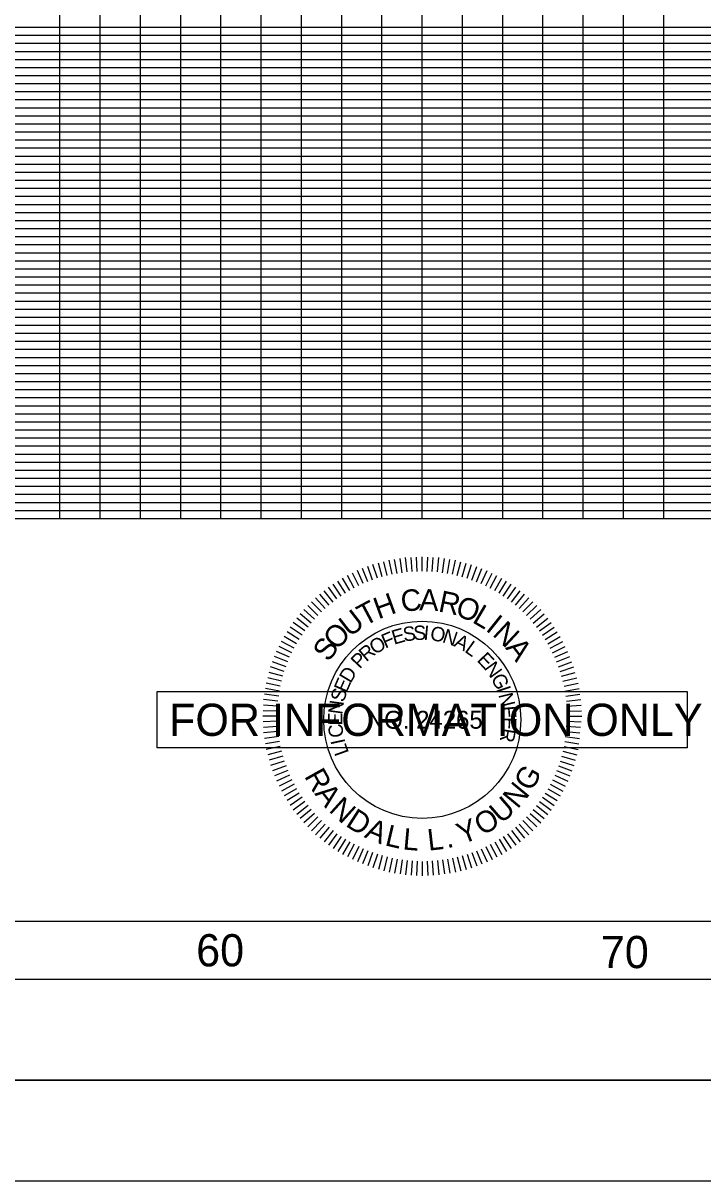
# Model space of a CAD drawing. Extents: x -15 to 165, y -6 to 109.
# Drawn here: x 135.09 to 151.97, y -6.45 to 22.3 of the extents above; entities that cross this region are included whole.
import ezdxf

# ---------------------------------------------------------------- set-up
doc = ezdxf.new("R2010")
doc.units = 0
for name, color, linetype in [('RD_SHT_Bndy', 7, 'Continuous'), ('RD_SHT_IplotShp', 7, 'Continuous'), ('RD_SHT_MjGrid', 7, 'Continuous'), ('RD_SHT_MnGrid', 7, 'Continuous'), ('RD_SHT_SubGrid', 7, 'Continuous'), ('RD_SHT_TX', 7, 'Continuous'), ('RD_TX_PEShield', 7, 'Continuous'), ('RD_XS_TX_Notes', 7, 'Continuous')]:
    doc.layers.add(name, color=color, linetype=linetype)

msp = doc.modelspace()

# ---------------------------------------------------------------- linework, layer by layer
at = {"layer": 'RD_SHT_Bndy'}
for p, q in [((-12.73, -3.949), (163.27, -3.949)), ((-12.73, -6.449), (163.27, -6.449))]:
    msp.add_line(p, q, dxfattribs=at)
msp.add_lwpolyline([(-4.99, 103.551), (162.51, 103.551), (162.51, -1.449), (-4.99, -1.449)], close=True, dxfattribs=at)
at = {"layer": 'RD_SHT_IplotShp'}
msp.add_lwpolyline([(-14.589, 106.051), (165.01, 106.051), (165.01, -3.949), (-14.589, -3.949)], close=True, dxfattribs=at)
at = {"layer": 'RD_SHT_MjGrid'}
for p, q in [((140, 10), (140, 100)), ((145, 10), (145, 100)), ((150, 10), (150, 100)), ((0, 20), (160, 20)), ((0, 15), (160, 15)), ((0, 10), (160, 10)), ((0, 0), (160, 0))]:
    msp.add_line(p, q, dxfattribs=at)
at = {"layer": 'RD_SHT_MnGrid'}
for p, q in [((136, 10), (136, 100)), ((137, 10), (137, 100)), ((138, 10), (138, 100)), ((139, 10), (139, 100)), ((141, 10), (141, 100)), ((142, 10), (142, 100)), ((143, 10), (143, 100)), ((144, 10), (144, 100)), ((146, 10), (146, 100)), ((147, 10), (147, 100)), ((148, 10), (148, 100)), ((149, 10), (149, 100)), ((151, 10), (151, 100)), ((0, 22), (160, 22)), ((0, 21), (160, 21)), ((0, 19), (160, 19)), ((0, 18), (160, 18)), ((0, 17), (160, 17)), ((0, 16), (160, 16)), ((0, 14), (160, 14)), ((0, 13), (160, 13)), ((0, 12), (160, 12)), ((0, 11), (160, 11))]:
    msp.add_line(p, q, dxfattribs=at)
at = {"layer": 'RD_SHT_SubGrid'}
for p, q in [((0, 22.2), (160, 22.2)), ((0, 21.8), (160, 21.8)), ((0, 21.6), (160, 21.6)), ((0, 21.4), (160, 21.4)), ((0, 21.2), (160, 21.2)), ((0, 20.8), (160, 20.8)), ((0, 20.6), (160, 20.6)), ((0, 20.4), (160, 20.4)), ((0, 20.2), (160, 20.2)), ((0, 19.8), (160, 19.8)), ((0, 19.6), (160, 19.6)), ((0, 19.4), (160, 19.4)), ((0, 19.2), (160, 19.2)), ((0, 18.8), (160, 18.8)), ((0, 18.6), (160, 18.6)), ((0, 18.4), (160, 18.4)), ((0, 18.2), (160, 18.2)), ((0, 17.8), (160, 17.8)), ((0, 17.6), (160, 17.6)), ((0, 17.4), (160, 17.4)), ((0, 17.2), (160, 17.2)), ((0, 16.8), (160, 16.8)), ((0, 16.6), (160, 16.6)), ((0, 16.4), (160, 16.4)), ((0, 16.2), (160, 16.2)), ((0, 15.8), (160, 15.8)), ((0, 15.6), (160, 15.6)), ((0, 15.4), (160, 15.4)), ((0, 15.2), (160, 15.2)), ((0, 14.8), (160, 14.8)), ((0, 14.6), (160, 14.6)), ((0, 14.4), (160, 14.4)), ((0, 14.2), (160, 14.2)), ((0, 13.8), (160, 13.8)), ((0, 13.6), (160, 13.6)), ((0, 13.4), (160, 13.4)), ((0, 13.2), (160, 13.2)), ((0, 12.8), (160, 12.8)), ((0, 12.6), (160, 12.6)), ((0, 12.4), (160, 12.4)), ((0, 12.2), (160, 12.2)), ((0, 11.8), (160, 11.8)), ((0, 11.6), (160, 11.6)), ((0, 11.4), (160, 11.4)), ((0, 11.2), (160, 11.2)), ((0, 10.8), (160, 10.8)), ((0, 10.6), (160, 10.6)), ((0, 10.4), (160, 10.4)), ((0, 10.2), (160, 10.2))]:
    msp.add_line(p, q, dxfattribs=at)
at = {"layer": 'RD_TX_PEShield'}
for p, q in [((144.129, 8.581), (144.043, 8.926)), ((144.129, 8.581), (144.043, 8.926)), ((144.251, 8.614), (144.177, 8.962)), ((144.251, 8.614), (144.177, 8.962)), ((144.375, 8.633), (144.313, 8.983)), ((144.375, 8.633), (144.313, 8.983)), ((144.499, 8.653), (144.449, 9.005)), ((144.499, 8.653), (144.449, 9.005)), ((144.623, 8.673), (144.586, 9.027)), ((144.623, 8.673), (144.586, 9.027)), ((144.749, 8.679), (144.724, 9.034)), ((144.749, 8.679), (144.724, 9.034)), ((144.874, 8.686), (144.862, 9.041)), ((144.874, 8.686), (144.862, 9.041)), ((145, 8.692), (145, 9.048)), ((145, 8.692), (145, 9.048)), ((145.126, 8.686), (145.138, 9.041)), ((145.126, 8.686), (145.138, 9.041)), ((145.251, 8.679), (145.276, 9.034)), ((145.251, 8.679), (145.276, 9.034)), ((145.377, 8.673), (145.414, 9.027)), ((145.377, 8.673), (145.414, 9.027)), ((145.501, 8.653), (145.551, 9.005)), ((145.501, 8.653), (145.551, 9.005)), ((145.625, 8.633), (145.687, 8.983)), ((145.625, 8.633), (145.687, 8.983)), ((145.749, 8.614), (145.823, 8.962)), ((145.749, 8.614), (145.823, 8.962)), ((145.749, 8.614), (145.823, 8.962)), ((145.871, 8.581), (145.957, 8.926)), ((145.871, 8.581), (145.957, 8.926)), ((145.871, 8.581), (145.957, 8.926)), ((143.422, 8.324), (143.266, 8.643)), ((143.422, 8.324), (143.266, 8.643)), ((143.534, 8.381), (143.389, 8.706)), ((143.534, 8.381), (143.389, 8.706)), ((143.651, 8.426), (143.518, 8.755)), ((143.651, 8.426), (143.518, 8.755)), ((143.769, 8.471), (143.647, 8.805)), ((143.769, 8.471), (143.647, 8.805)), ((143.886, 8.516), (143.776, 8.854)), ((143.886, 8.516), (143.776, 8.854)), ((144.008, 8.548), (143.91, 8.89)), ((144.008, 8.548), (143.91, 8.89)), ((145.992, 8.548), (146.09, 8.89)), ((145.992, 8.548), (146.09, 8.89)), ((145.992, 8.548), (146.09, 8.89)), ((146.114, 8.516), (146.224, 8.854)), ((146.114, 8.516), (146.224, 8.854)), ((146.114, 8.516), (146.224, 8.854)), ((146.231, 8.471), (146.353, 8.805)), ((146.231, 8.471), (146.353, 8.805)), ((146.231, 8.471), (146.353, 8.805)), ((146.349, 8.426), (146.482, 8.755)), ((146.349, 8.426), (146.482, 8.755)), ((146.349, 8.426), (146.482, 8.755)), ((146.466, 8.381), (146.611, 8.706)), ((146.466, 8.381), (146.611, 8.706)), ((146.466, 8.381), (146.611, 8.706)), ((146.578, 8.324), (146.734, 8.643)), ((146.578, 8.324), (146.734, 8.643)), ((146.578, 8.324), (146.734, 8.643)), ((142.987, 8.072), (142.788, 8.367)), ((142.987, 8.072), (142.788, 8.367)), ((143.092, 8.141), (142.904, 8.442)), ((143.092, 8.141), (142.904, 8.442)), ((143.198, 8.209), (143.02, 8.518)), ((143.198, 8.209), (143.02, 8.518)), ((143.31, 8.267), (143.143, 8.58)), ((143.31, 8.267), (143.143, 8.58)), ((146.69, 8.267), (146.857, 8.58)), ((146.69, 8.267), (146.857, 8.58)), ((146.69, 8.267), (146.857, 8.58)), ((146.802, 8.209), (146.98, 8.518)), ((146.802, 8.209), (146.98, 8.518)), ((146.802, 8.209), (146.98, 8.518)), ((146.908, 8.141), (147.096, 8.442)), ((146.908, 8.141), (147.096, 8.442)), ((146.908, 8.141), (147.096, 8.442)), ((147.013, 8.072), (147.212, 8.367)), ((147.013, 8.072), (147.212, 8.367)), ((147.013, 8.072), (147.212, 8.367)), ((142.686, 7.846), (142.457, 8.118)), ((142.686, 7.846), (142.457, 8.118)), ((142.784, 7.925), (142.565, 8.205)), ((142.784, 7.925), (142.565, 8.205)), ((142.881, 8.004), (142.672, 8.292)), ((142.881, 8.004), (142.672, 8.292)), ((147.119, 8.004), (147.328, 8.292)), ((147.119, 8.004), (147.328, 8.292)), ((147.119, 8.004), (147.328, 8.292)), ((147.216, 7.925), (147.435, 8.205)), ((147.216, 7.925), (147.435, 8.205)), ((147.216, 7.925), (147.435, 8.205)), ((147.314, 7.846), (147.543, 8.118)), ((147.314, 7.846), (147.543, 8.118)), ((147.314, 7.846), (147.543, 8.118)), ((142.41, 7.589), (142.155, 7.836)), ((142.41, 7.589), (142.155, 7.836)), ((142.499, 7.678), (142.252, 7.933)), ((142.499, 7.678), (142.252, 7.933)), ((142.588, 7.766), (142.35, 8.031)), ((142.588, 7.766), (142.35, 8.031)), ((147.412, 7.766), (147.65, 8.031)), ((147.412, 7.766), (147.65, 8.031)), ((147.412, 7.766), (147.65, 8.031)), ((147.501, 7.678), (147.748, 7.933)), ((147.501, 7.678), (147.748, 7.933)), ((147.501, 7.678), (147.748, 7.933)), ((147.59, 7.589), (147.845, 7.836)), ((147.59, 7.589), (147.845, 7.836)), ((147.59, 7.589), (147.845, 7.836)), ((142.163, 7.304), (141.883, 7.523)), ((142.163, 7.304), (141.883, 7.523)), ((142.242, 7.402), (141.97, 7.63)), ((142.242, 7.402), (141.97, 7.63)), ((142.321, 7.5), (142.057, 7.738)), ((142.321, 7.5), (142.057, 7.738)), ((147.679, 7.5), (147.943, 7.738)), ((147.679, 7.5), (147.943, 7.738)), ((147.679, 7.5), (147.943, 7.738)), ((147.758, 7.402), (148.03, 7.63)), ((147.758, 7.402), (148.03, 7.63)), ((147.758, 7.402), (148.03, 7.63)), ((147.837, 7.304), (148.117, 7.523)), ((147.837, 7.304), (148.117, 7.523)), ((147.837, 7.304), (148.117, 7.523)), ((142.015, 7.101), (141.721, 7.3)), ((142.015, 7.101), (141.721, 7.3)), ((142.084, 7.206), (141.796, 7.416)), ((142.084, 7.206), (141.796, 7.416)), ((147.916, 7.206), (148.204, 7.416)), ((147.916, 7.206), (148.204, 7.416)), ((147.916, 7.206), (148.204, 7.416)), ((147.985, 7.101), (148.279, 7.3)), ((147.985, 7.101), (148.279, 7.3)), ((147.985, 7.101), (148.279, 7.3)), ((141.821, 6.778), (141.507, 6.945)), ((141.821, 6.778), (141.507, 6.945)), ((141.878, 6.89), (141.57, 7.068)), ((141.878, 6.89), (141.57, 7.068)), ((141.947, 6.996), (141.645, 7.184)), ((141.947, 6.996), (141.645, 7.184)), ((148.053, 6.996), (148.355, 7.184)), ((148.053, 6.996), (148.355, 7.184)), ((148.053, 6.996), (148.355, 7.184)), ((148.122, 6.89), (148.43, 7.068)), ((148.122, 6.89), (148.43, 7.068)), ((148.122, 6.89), (148.43, 7.068)), ((148.179, 6.778), (148.493, 6.945)), ((148.179, 6.778), (148.493, 6.945)), ((148.179, 6.778), (148.493, 6.945)), ((141.707, 6.554), (141.382, 6.699)), ((141.707, 6.554), (141.382, 6.699)), ((141.764, 6.666), (141.445, 6.822)), ((141.764, 6.666), (141.445, 6.822)), ((148.236, 6.666), (148.555, 6.822)), ((148.236, 6.666), (148.555, 6.822)), ((148.236, 6.666), (148.555, 6.822)), ((148.293, 6.554), (148.618, 6.699)), ((148.293, 6.554), (148.618, 6.699)), ((148.293, 6.554), (148.618, 6.699)), ((141.617, 6.319), (141.283, 6.441)), ((141.617, 6.319), (141.283, 6.441)), ((141.662, 6.436), (141.332, 6.57)), ((141.662, 6.436), (141.332, 6.57)), ((148.338, 6.436), (148.668, 6.57)), ((148.338, 6.436), (148.668, 6.57)), ((148.338, 6.436), (148.668, 6.57)), ((148.383, 6.319), (148.717, 6.441)), ((148.383, 6.319), (148.717, 6.441)), ((148.383, 6.319), (148.717, 6.441)), ((141.507, 5.959), (141.162, 6.045)), ((141.507, 5.959), (141.162, 6.045)), ((141.539, 6.08), (141.198, 6.178)), ((141.539, 6.08), (141.198, 6.178)), ((141.572, 6.202), (141.233, 6.312)), ((141.572, 6.202), (141.233, 6.312)), ((148.428, 6.202), (148.767, 6.312)), ((148.428, 6.202), (148.767, 6.312)), ((148.428, 6.202), (148.767, 6.312)), ((148.461, 6.08), (148.802, 6.178)), ((148.461, 6.08), (148.802, 6.178)), ((148.461, 6.08), (148.802, 6.178)), ((148.493, 5.959), (148.838, 6.045)), ((148.493, 5.959), (148.838, 6.045)), ((148.493, 5.959), (148.838, 6.045)), ((141.455, 5.713), (141.104, 5.775)), ((141.455, 5.713), (141.104, 5.775)), ((141.474, 5.837), (141.126, 5.911)), ((141.474, 5.837), (141.126, 5.911)), ((148.526, 5.837), (148.874, 5.911)), ((148.526, 5.837), (148.874, 5.911)), ((148.526, 5.837), (148.874, 5.911)), ((148.545, 5.713), (148.896, 5.775)), ((148.545, 5.713), (148.896, 5.775)), ((148.545, 5.713), (148.896, 5.775)), ((141.415, 5.465), (141.061, 5.502)), ((141.415, 5.465), (141.061, 5.502)), ((141.435, 5.589), (141.083, 5.638)), ((141.435, 5.589), (141.083, 5.638)), ((148.565, 5.589), (148.917, 5.638)), ((148.565, 5.589), (148.917, 5.638)), ((148.565, 5.589), (148.917, 5.638)), ((148.585, 5.465), (148.939, 5.502)), ((148.585, 5.465), (148.939, 5.502)), ((148.585, 5.465), (148.939, 5.502)), ((141.402, 5.213), (141.047, 5.226)), ((141.402, 5.213), (141.047, 5.226)), ((141.409, 5.339), (141.054, 5.364)), ((141.409, 5.339), (141.054, 5.364)), ((148.591, 5.339), (148.946, 5.364)), ((148.591, 5.339), (148.946, 5.364)), ((148.591, 5.339), (148.946, 5.364)), ((148.598, 5.213), (148.953, 5.226)), ((148.598, 5.213), (148.953, 5.226)), ((148.598, 5.213), (148.953, 5.226)), ((141.396, 5.088), (141.04, 5.088)), ((141.396, 5.088), (141.04, 5.088)), ((141.402, 4.962), (141.047, 4.95)), ((141.402, 4.962), (141.047, 4.95)), ((148.591, 4.962), (148.946, 4.95)), ((148.591, 4.962), (148.946, 4.95)), ((148.605, 5.088), (148.961, 5.088)), ((148.605, 5.088), (148.961, 5.088)), ((148.605, 5.088), (148.961, 5.088)), ((141.409, 4.837), (141.054, 4.812)), ((141.409, 4.837), (141.054, 4.812)), ((141.415, 4.711), (141.061, 4.674)), ((141.415, 4.711), (141.061, 4.674)), ((148.565, 4.713), (148.917, 4.676)), ((148.565, 4.713), (148.917, 4.676)), ((148.578, 4.838), (148.932, 4.813)), ((148.578, 4.838), (148.932, 4.813)), ((141.435, 4.587), (141.083, 4.537)), ((141.435, 4.587), (141.083, 4.537)), ((141.455, 4.463), (141.104, 4.401)), ((141.455, 4.463), (141.104, 4.401)), ((141.474, 4.338), (141.126, 4.264)), ((141.474, 4.338), (141.126, 4.264)), ((148.526, 4.338), (148.874, 4.264)), ((148.526, 4.338), (148.874, 4.264)), ((148.539, 4.464), (148.888, 4.402)), ((148.539, 4.464), (148.888, 4.402)), ((148.552, 4.589), (148.903, 4.539)), ((148.552, 4.589), (148.903, 4.539)), ((141.507, 4.217), (141.162, 4.131)), ((141.507, 4.217), (141.162, 4.131)), ((141.539, 4.095), (141.198, 3.997)), ((141.539, 4.095), (141.198, 3.997)), ((148.461, 4.095), (148.802, 3.997)), ((148.461, 4.095), (148.802, 3.997)), ((148.493, 4.217), (148.838, 4.131)), ((148.493, 4.217), (148.838, 4.131)), ((141.572, 3.974), (141.233, 3.864)), ((141.617, 3.856), (141.283, 3.735)), ((141.617, 3.856), (141.283, 3.735)), ((141.662, 3.739), (141.332, 3.606)), ((141.662, 3.739), (141.332, 3.606)), ((148.338, 3.739), (148.668, 3.606)), ((148.338, 3.739), (148.668, 3.606)), ((148.383, 3.856), (148.717, 3.735)), ((148.383, 3.856), (148.717, 3.735)), ((148.428, 3.974), (148.767, 3.864)), ((148.428, 3.974), (148.767, 3.864)), ((141.707, 3.622), (141.382, 3.477)), ((141.707, 3.622), (141.382, 3.477)), ((141.764, 3.51), (141.445, 3.354)), ((141.764, 3.51), (141.445, 3.354)), ((148.236, 3.51), (148.555, 3.354)), ((148.236, 3.51), (148.555, 3.354)), ((148.293, 3.622), (148.618, 3.477)), ((148.293, 3.622), (148.618, 3.477)), ((141.821, 3.398), (141.507, 3.231)), ((141.821, 3.398), (141.507, 3.231)), ((141.878, 3.286), (141.57, 3.108)), ((141.878, 3.286), (141.57, 3.108)), ((141.947, 3.18), (141.645, 2.992)), ((141.947, 3.18), (141.645, 2.992)), ((148.053, 3.18), (148.355, 2.992)), ((148.053, 3.18), (148.355, 2.992)), ((148.122, 3.286), (148.43, 3.108)), ((148.122, 3.286), (148.43, 3.108)), ((148.179, 3.398), (148.493, 3.231)), ((148.179, 3.398), (148.493, 3.231)), ((142.015, 3.075), (141.721, 2.876)), ((142.015, 3.075), (141.721, 2.876)), ((142.084, 2.969), (141.796, 2.76)), ((142.084, 2.969), (141.796, 2.76)), ((147.916, 2.969), (148.204, 2.76)), ((147.916, 2.969), (148.204, 2.76)), ((147.985, 3.075), (148.279, 2.876)), ((147.985, 3.075), (148.279, 2.876)), ((142.163, 2.871), (141.883, 2.652)), ((142.163, 2.871), (141.883, 2.652)), ((142.242, 2.774), (141.97, 2.545)), ((142.242, 2.774), (141.97, 2.545)), ((142.321, 2.676), (142.057, 2.438)), ((142.321, 2.676), (142.057, 2.438)), ((147.679, 2.676), (147.943, 2.438)), ((147.679, 2.676), (147.943, 2.438)), ((147.758, 2.774), (148.03, 2.545)), ((147.758, 2.774), (148.03, 2.545)), ((147.837, 2.871), (148.117, 2.652)), ((147.837, 2.871), (148.117, 2.652)), ((142.41, 2.587), (142.155, 2.34)), ((142.41, 2.587), (142.155, 2.34)), ((142.499, 2.498), (142.252, 2.242)), ((142.499, 2.498), (142.252, 2.242)), ((142.588, 2.409), (142.35, 2.145)), ((142.588, 2.409), (142.35, 2.145)), ((142.686, 2.33), (142.457, 2.058)), ((142.686, 2.33), (142.457, 2.058)), ((147.314, 2.33), (147.543, 2.058)), ((147.314, 2.33), (147.543, 2.058)), ((147.412, 2.409), (147.65, 2.145)), ((147.501, 2.498), (147.748, 2.242)), ((147.501, 2.498), (147.748, 2.242)), ((147.59, 2.587), (147.845, 2.34)), ((147.59, 2.587), (147.845, 2.34)), ((142.784, 2.251), (142.565, 1.971)), ((142.784, 2.251), (142.565, 1.971)), ((142.881, 2.172), (142.672, 1.884)), ((142.881, 2.172), (142.672, 1.884)), ((142.987, 2.103), (142.788, 1.808)), ((142.987, 2.103), (142.788, 1.808)), ((143.092, 2.035), (142.904, 1.733)), ((143.092, 2.035), (142.904, 1.733)), ((146.908, 2.035), (147.096, 1.733)), ((146.908, 2.035), (147.096, 1.733)), ((147.013, 2.103), (147.212, 1.808)), ((147.013, 2.103), (147.212, 1.808)), ((147.119, 2.172), (147.328, 1.884)), ((147.119, 2.172), (147.328, 1.884)), ((147.216, 2.251), (147.435, 1.971)), ((147.216, 2.251), (147.435, 1.971)), ((143.198, 1.966), (143.02, 1.658)), ((143.198, 1.966), (143.02, 1.658)), ((143.31, 1.909), (143.143, 1.595)), ((143.31, 1.909), (143.143, 1.595)), ((143.422, 1.852), (143.266, 1.532)), ((143.422, 1.852), (143.266, 1.532)), ((143.534, 1.795), (143.389, 1.47)), ((143.534, 1.795), (143.389, 1.47)), ((143.651, 1.75), (143.518, 1.42)), ((143.651, 1.75), (143.518, 1.42)), ((146.349, 1.75), (146.482, 1.42)), ((146.349, 1.75), (146.482, 1.42)), ((146.466, 1.795), (146.611, 1.47)), ((146.466, 1.795), (146.611, 1.47)), ((146.578, 1.852), (146.734, 1.532)), ((146.578, 1.852), (146.734, 1.532)), ((146.69, 1.909), (146.857, 1.595)), ((146.69, 1.909), (146.857, 1.595)), ((146.802, 1.966), (146.98, 1.658)), ((146.802, 1.966), (146.98, 1.658)), ((143.769, 1.705), (143.647, 1.371)), ((143.769, 1.705), (143.647, 1.371)), ((143.886, 1.66), (143.776, 1.321)), ((143.886, 1.66), (143.776, 1.321)), ((144.008, 1.627), (143.91, 1.285)), ((144.008, 1.627), (143.91, 1.285)), ((144.129, 1.595), (144.043, 1.25)), ((144.129, 1.595), (144.043, 1.25)), ((144.251, 1.562), (144.177, 1.214)), ((144.251, 1.562), (144.177, 1.214)), ((144.375, 1.542), (144.313, 1.192)), ((144.375, 1.542), (144.313, 1.192)), ((144.499, 1.523), (144.449, 1.171)), ((144.499, 1.523), (144.449, 1.171)), ((144.623, 1.503), (144.586, 1.149)), ((144.623, 1.503), (144.586, 1.149)), ((144.749, 1.496), (144.724, 1.142)), ((144.749, 1.496), (144.724, 1.142)), ((144.874, 1.49), (144.862, 1.135)), ((144.874, 1.49), (144.862, 1.135)), ((145, 1.483), (145, 1.127)), ((145, 1.483), (145, 1.127)), ((145.126, 1.49), (145.138, 1.135)), ((145.126, 1.49), (145.138, 1.135)), ((145.251, 1.496), (145.276, 1.142)), ((145.251, 1.496), (145.276, 1.142)), ((145.377, 1.503), (145.414, 1.149)), ((145.377, 1.503), (145.414, 1.149)), ((145.501, 1.523), (145.551, 1.171)), ((145.501, 1.523), (145.551, 1.171)), ((145.625, 1.542), (145.687, 1.192)), ((145.625, 1.542), (145.687, 1.192)), ((145.749, 1.562), (145.823, 1.214)), ((145.749, 1.562), (145.823, 1.214)), ((145.871, 1.595), (145.957, 1.25)), ((145.871, 1.595), (145.957, 1.25)), ((145.992, 1.627), (146.09, 1.285)), ((145.992, 1.627), (146.09, 1.285)), ((146.114, 1.66), (146.224, 1.321)), ((146.114, 1.66), (146.224, 1.321)), ((146.231, 1.705), (146.353, 1.371)), ((146.231, 1.705), (146.353, 1.371))]:
    msp.add_line(p, q, dxfattribs=at)
msp.add_circle((145, 5), 2.448, dxfattribs=at)
at = {"layer": 'RD_XS_TX_Notes'}
msp.add_lwpolyline([(138.418, 5.7), (151.582, 5.7), (151.582, 4.3), (138.418, 4.3)], close=True, dxfattribs=at)

# ---------------------------------------------------------------- texts
at = {"layer": 'RD_SHT_TX'}
for s, p in [('60', (139.385, -1.123)), ('70', (149.438, -1.167))]:
    msp.add_text(s, height=0.8, dxfattribs=at).set_placement(p)
at = {"layer": 'RD_TX_PEShield'}
for s, height, rotation, p in [('H', 0.534, 19.9102, (143.91, 7.492)), ('C', 0.534, 6.8832, (144.499, 7.674)), ('A', 0.534, 357.9448, (144.921, 7.719)), ('R', 0.534, 348.267, (145.379, 7.694)), ('O', 0.534, 339.3286, (145.793, 7.602)), ('T', 0.534, 28.0947, (143.566, 7.312)), ('L', 0.534, 329.6507, (146.219, 7.432)), ('U', 0.534, 37.7726, (143.198, 7.038)), ('I', 0.534, 321.4663, (146.553, 7.233)), ('O', 0.534, 47.4504, (142.881, 6.706)), ('F', 0.356, 23.0853, (144.081, 6.766)), ('E', 0.356, 16.1843, (144.3, 6.863)), ('S', 0.356, 8.6909, (144.549, 6.939)), ('S', 0.356, 1.79, (144.785, 6.979)), ('I', 0.356, 354.889, (145.024, 6.99)), ('O', 0.356, 350.4045, (145.18, 6.982)), ('N', 0.356, 341.7029, (145.478, 6.932)), ('N', 0.534, 317.0007, (146.722, 7.106)), ('S', 0.534, 54.9027, (142.678, 6.416)), ('O', 0.356, 31.7869, (143.824, 6.606)), ('A', 0.356, 333.0013, (145.765, 6.838)), ('L', 0.356, 324.2997, (146.034, 6.701)), ('A', 0.534, 307.3229, (147.052, 6.786)), ('P', 0.356, 46.7912, (143.449, 6.247)), ('R', 0.356, 39.8902, (143.61, 6.425)), ('E', 0.356, 313.2251, (146.341, 6.471)), ('N', 0.356, 305.7317, (146.522, 6.283)), ('E', 0.356, 66.5674, (143.118, 5.649)), ('D', 0.356, 59.074, (143.219, 5.889)), ('G', 0.356, 297.0301, (146.698, 6.038)), ('S', 0.356, 73.4683, (143.054, 5.418)), ('I', 0.356, 288.3285, (146.836, 5.769)), ('N', 0.356, 82.17, (143.013, 5.119)), ('N', 0.356, 283.8441, (146.89, 5.624)), ('E', 0.356, 275.1424, (146.963, 5.33)), ('E', 0.356, 89.6633, (143.014, 4.859)), ('C', 0.356, 97.7667, (143.054, 4.58)), ('E', 0.356, 267.6491, (146.989, 5.072)), ('R', 0.356, 260.1557, (146.982, 4.811)), ('I', 0.356, 102.2511, (143.093, 4.429)), ('L', 0.356, 109.7445, (143.184, 4.185)), ('R', 0.534, 299.1493, (142.06, 3.603)), ('G', 0.534, 60.1113, (147.711, 3.198)), ('N', 0.534, 50.4335, (147.369, 2.768)), ('A', 0.534, 308.0877, (142.313, 3.163)), ('N', 0.534, 317.7655, (142.66, 2.737)), ('U', 0.534, 40.7556, (146.96, 2.401)), ('D', 0.534, 327.4433, (143.073, 2.376)), ('O', 0.534, 31.0778, (146.496, 2.108)), ('A', 0.534, 337.1212, (143.542, 2.089)), ('L', 0.534, 346.799, (144.052, 1.886)), ('L', 0.534, 354.9835, (144.505, 1.782)), ('Y', 0.534, 21.4, (145.988, 1.898)), ('L', 0.534, 6.5171, (145.158, 1.748)), ('.', 0.534, 14.7016, (145.62, 1.804))]:
    msp.add_text(s, height=height, rotation=rotation, dxfattribs=at).set_placement(p)
msp.add_text('NO. 24265', height=0.445, dxfattribs=at).set_placement((143.625, 4.778))
at = {"layer": 'RD_XS_TX_Notes'}
msp.add_text('FOR INFORMATION ONLY', height=0.8, dxfattribs=at).set_placement((138.712, 4.6))

doc.saveas('drawing.dxf')
